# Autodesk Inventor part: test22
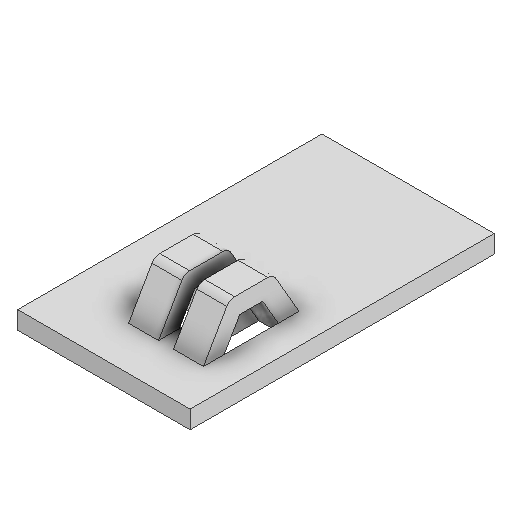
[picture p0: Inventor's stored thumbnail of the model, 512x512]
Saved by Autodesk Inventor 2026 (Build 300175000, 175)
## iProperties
Created: 2025-08
Part Number: test22
Material: Generic
Document SubType Name: Sheet Metal
Designer: sup1
Density: 1 g/cm^3
Sheet Metal Rule: Default
Appearance: Default
Author: sup1
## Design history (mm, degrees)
node "Face1"
  sketch "Sketch1"
    geometry: L1 (14.151, 25.813)-(-15.097, 25.813); L2 (-15.097, 25.813)-(-15.097, -25.813); L3 (-15.097, -25.813)-(14.151, -25.813); L4 (14.151, -25.813)-(14.151, 25.813)
    constraints: 8 end point, 2 parallel, 1 horizontal, 1 perpendicular
sketch "Sketch2"
  geometry: L1 (9.97, -16.655)-(4.89, -16.655); L2 (4.89, -16.655)-(4.89, -3.955); L3 (4.89, -3.955)-(9.97, -3.955); L4 (9.97, -3.955)-(9.97, -16.655); L5 (9.97, -16.655)-(4.89, -3.955); L6 (4.89, -16.655)-(9.97, -3.955); L7 (2.35, -3.955)-(-2.73, -3.955); L8 (-2.73, -3.955)-(-2.73, -16.655); L9 (-2.73, -16.655)-(2.35, -16.655); L10 (2.35, -16.655)-(2.35, -3.955); L11 (2.35, -3.955)-(-2.73, -16.655); L12 (-2.73, -3.955)-(2.35, -16.655); 3 further points
  constraints: 24 end point, 4 midpoint, 4 parallel, 2 equal length, 2 horizontal, 2 perpendicular
  dimensions: "Length" = 12.7 distance of L3.end L1.start; "d2" = 3.81 distance of point (7.43, -10.305) point (3.62, -10.305) (= 0.5 x Gap + 0.5 x Slot); "d3" = 5.08 distance of L1.start L1.end (= Slot); "d4" = 3.81 distance of point (-0.19, -10.305) point (3.62, -10.305) (= d2); "d5" = 6.35 distance from line of L9 point (3.62, -10.305) (= 0.5 x Length); "d6" = 6.35 distance from line of L3 point (3.62, -10.305) (= d5)
extrude "Extrusion1" cut sketch "Sketch2" distance "d7" = 3.048 (= Thickness); taper "d8" = 0 deg
workplane "Work Plane1"
sketch "Sketch3"
  geometry: L1 (12.7, -3.048)-(15.34, -1.524); L2 (15.34, -1.524)-(10.06, 7.62); L3 (10.06, 7.62)-(2.64, 7.62); L4 (2.64, 7.62)-(-2.64, -1.524); L5 (-2.64, -1.524)-(0, -3.048); L6 (0, -3.048)-(4.399, 4.572); L7 (4.399, 4.572)-(8.301, 4.572); L8 (8.301, 4.572)-(12.7, -3.048); L9 (12.7, 0)-(0, 0) reference; 2 further points
  constraints: 16 end point, 4 parallel, 2 perpendicular, 1 midpoint
  dimensions: "d9" = 3.048 distance between parallel lines of L6 L4 (= Thickness); "d10" = 3.048 distance between parallel lines of L8 L2 (= Thickness); "d11" = 6.35 horizontal distance of point (6.35, 0) L5.end (= d5); "d12" = 6.35 horizontal distance of point (6.35, 0) L1.start (= d6); "d13" = 3.048 distance from line of L1.start L9 (= Thickness); "d14" = 3.048 distance from line of L9 L5.end (= Thickness); "Angle" = 60 deg angle of L6 L9; "d16" = 60 deg angle of L8 L9 (= Angle); "Height" = 7.62 distance between parallel lines of L9 L3; "d20" = 4.572 distance between parallel lines of L9 L7 (= Height - Thickness)
extrude "Extrusion2" join sketch "Sketch3" stored distance "d21" = 5.08 (= Slot); taper "d22" = 0 deg
fillet "Fillet1" dims "d26" = 1.524 (= 0.5 x Thickness)
pattern_linear "Rectangular Pattern1" dims "d25" = 7.62 (= Width - Slot)
body "Solid1"
face "Plate1" dims "d0" = 3.048 (= Thickness)
other parameters: "Thickness" = 3.048, "BendRadius" = 3.048 (= Thickness), "BendReliefWidth" = 3.048 (= Thickness), "BendReliefDepth" = 1.524 (= 0.5 x Thickness), "CornerReliefSize" = 12.192 (= 4 x Thickness), "SeamGap" = 0.00508, "MinimumRemnant" = 6.096 (= 2 x Thickness), "TransitionRadius" = 3.048 (= BendRadius), "JacobiRadiusSize" = 3.048 (= BendRadius), "GapSize" = 3.048 (= Thickness), "Gap" = 2.54 [user parameter; used in 2 equation terms], "Slot" = 5.08 (= -0.5 x Gap + 0.5 x Width) [user parameter; used in 4 equation terms], "Width" = 12.7 [user parameter; used in 2 equation terms]
